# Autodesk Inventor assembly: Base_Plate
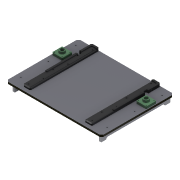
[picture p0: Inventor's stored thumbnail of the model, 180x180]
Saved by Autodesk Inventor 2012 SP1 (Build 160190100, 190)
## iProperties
Created: 2005-12
Part Number: Base_Plate
Document SubType Name: Assembly
Designer: Neil
Author: Neil
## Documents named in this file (6)
- D:\AOTC\Autodesk Inventor 2012 Essential for New Users\Autodesk Inventor 2012 Essentials - Project Files\Learning\Workspace\Sub-Assemblies\Base_Plate.iam
- D:\AOTC\Autodesk Inventor 2012 Essential for New Users\Autodesk Inventor 2012 Essentials - Project Files\Learning\Workspace\Parts\press-baseplate.ipt
- D:\AOTC\Autodesk Inventor 2012 Essential for New Users\Autodesk Inventor 2012 Essentials - Project Files\Learning\Workspace\Parts\press riser.ipt
- D:\AOTC\Autodesk Inventor 2012 Essential for New Users\Autodesk Inventor 2012 Essentials - Project Files\Learning\Workspace\Parts\lower left guide rail.ipt
- D:\AOTC\Autodesk Inventor 2012 Essential for New Users\Autodesk Inventor 2012 Essentials - Project Files\Learning\Workspace\Parts\lower right guide rail.ipt
- D:\AOTC\Autodesk Inventor 2012 Essential for New Users\Autodesk Inventor 2012 Essentials - Project Files\Learning\Workspace\Parts\TLM-2022.ipt
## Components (7 placed, 5 different names)
1. press-baseplate:1
2. press riser:1
3. press riser:2
4. TLM-2022:1
5. TLM-2022:2
6. lower left guide rail:1 — Angle:1
7. lower right guide rail:1 — Angle:1
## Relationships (1: Angle 1)
- Angle:1: lower left guide rail:1 ↔ lower right guide rail:1
